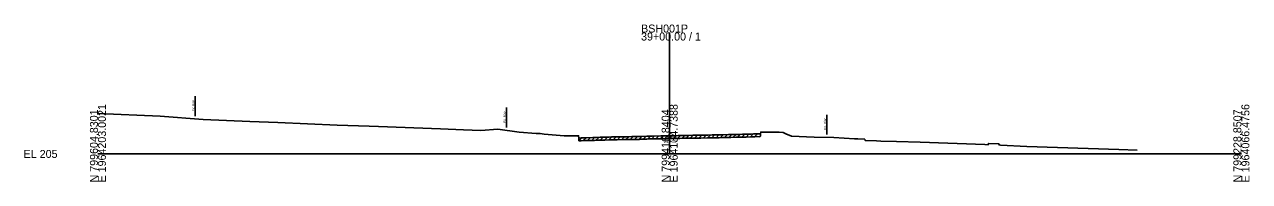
# Model space of a CAD drawing. Extents: x -26 to 1403, y -10 to 19587.
# Drawn here: x 974.3 to 1402.8, y 2990.3 to 3045.4 of the extents above; entities that cross this region are included whole.
import ezdxf

# ---------------------------------------------------------------- set-up
doc = ezdxf.new("R2010")
doc.units = 0
for name, color, linetype in [('Default', 7, 'Continuous'), ('RD_GPK_XS_Cell', 7, 'Continuous'), ('RD_XS_ExGround', 7, 'Continuous'), ('RD_XS_ExPaveRet', 7, 'Continuous'), ('RD_XS_ExRW', 7, 'Continuous'), ('RD_XS_TX_Elev_EX', 7, 'Continuous')]:
    doc.layers.add(name, color=color, linetype=linetype)

msp = doc.modelspace()

# ---------------------------------------------------------------- linework, layer by layer
at = {"layer": 'RD_GPK_XS_Cell'}
for p, q in [((1200, 3000), (1200, 3042.57)), ((1000, 3000), (1200, 3000)), ((1200, 3000), (1400, 3000))]:
    msp.add_line(p, q, dxfattribs=at)
at = {"layer": 'RD_XS_ExGround'}
msp.add_lwpolyline([(1000, 3014.19), (1021.82, 3013.19), (1036.85, 3012.04), (1053.19, 3011.37), (1062.94, 3010.97), (1083.68, 3010.09), (1094.83, 3009.69), (1098.19, 3009.56), (1119.78, 3008.79), (1127.84, 3008.44), (1133.92, 3008.16), (1139.86, 3008.66), (1147.36, 3007.64), (1153.27, 3007.2), (1154.72, 3007.11), (1156.1, 3006.98), (1163.13, 3006.38), (1165.49, 3006.35), (1168.12, 3006.37), (1168.19, 3005.55), (1169.06, 3005.64), (1170.25, 3005.67), (1170.89, 3005.68), (1173.15, 3005.74), (1173.74, 3005.76), (1174.27, 3005.77), (1175.71, 3005.82), (1176.22, 3005.84), (1177.3, 3005.87), (1178.87, 3005.93), (1179.6, 3005.95), (1181.59, 3005.99), (1184.16, 3006.02), (1185.43, 3006.04), (1186.82, 3006.06), (1188.89, 3006.1), (1189.47, 3006.11), (1189.91, 3006.12), (1192.03, 3006.19), (1192.86, 3006.24), (1193.89, 3006.27), (1196.95, 3006.35), (1197.67, 3006.34), (1198.82, 3006.35), (1200.14, 3006.35), (1202.35, 3006.4), (1202.99, 3006.41), (1203.55, 3006.43), (1204.97, 3006.48), (1205.47, 3006.49), (1206.15, 3006.5), (1206.75, 3006.51), (1208.13, 3006.54), (1210.9, 3006.57), (1213.43, 3006.61), (1214.88, 3006.64), (1216.09, 3006.66), (1217.36, 3006.69), (1218.62, 3006.72), (1220.54, 3006.78), (1221.38, 3006.8), (1223.19, 3006.84), (1224.05, 3006.86), (1225.53, 3006.9), (1226.39, 3006.92), (1226.71, 3006.93), (1228.35, 3006.98), (1229.36, 3007.01), (1229.83, 3007.03), (1230.72, 3007.06), (1231.52, 3007.05), (1231.78, 3007.2), (1231.88, 3007.65), (1235.01, 3007.68), (1236.92, 3007.67), (1238.32, 3007.59), (1239.75, 3007.48), (1240.69, 3007.09), (1242.66, 3006.17), (1250.54, 3005.87), (1257.41, 3005.71), (1264.7, 3005.33), (1265.88, 3005.3), (1268.27, 3005.17), (1268.37, 3004.72), (1272.32, 3004.55), (1273.88, 3004.47), (1279.38, 3004.35), (1287.62, 3004.07), (1310.23, 3003.25), (1311.43, 3003.21), (1311.53, 3003.66), (1315.15, 3003.59), (1315.25, 3003.14), (1315.77, 3003.11), (1324.96, 3002.57), (1357.12, 3001.58), (1363.52, 3001.36)], dxfattribs=at)
at = {"layer": 'RD_XS_ExPaveRet'}
for p, q in [((1168.22, 3004.55), (1169.31, 3005.64)), ((1168.22, 3004.55), (1168.22, 3005.55)), ((1168.22, 3004.55), (1169.06, 3004.64)), ((1169.06, 3004.64), (1170.25, 3004.67)), ((1169.72, 3004.65), (1170.74, 3005.67)), ((1170.25, 3004.67), (1170.89, 3004.68)), ((1170.89, 3004.68), (1173.15, 3004.74)), ((1171.22, 3004.69), (1172.25, 3005.71)), ((1172.72, 3004.73), (1173.75, 3005.76)), ((1173.15, 3004.74), (1173.74, 3004.76)), ((1173.74, 3004.76), (1174.27, 3004.77)), ((1174.22, 3004.77), (1175.26, 3005.81)), ((1174.27, 3004.77), (1175.71, 3004.82)), ((1175.71, 3004.82), (1176.22, 3004.84)), ((1175.72, 3004.82), (1176.76, 3005.86)), ((1176.22, 3004.84), (1177.3, 3004.87)), ((1177.22, 3004.87), (1178.26, 3005.91)), ((1177.3, 3004.87), (1178.87, 3004.93)), ((1178.72, 3004.92), (1179.75, 3005.95)), ((1178.87, 3004.93), (1179.6, 3004.95)), ((1179.6, 3004.95), (1181.59, 3004.99)), ((1180.22, 3004.96), (1181.24, 3005.99)), ((1181.59, 3004.99), (1184.16, 3005.02)), ((1181.72, 3004.99), (1182.73, 3006)), ((1183.22, 3005.01), (1184.23, 3006.02)), ((1184.16, 3005.02), (1185.43, 3005.04)), ((1184.72, 3005.02), (1185.74, 3006.04)), ((1185.43, 3005.04), (1186.82, 3005.06)), ((1186.22, 3005.05), (1187.24, 3006.07)), ((1186.82, 3005.06), (1188.89, 3005.1)), ((1187.72, 3005.08), (1188.74, 3006.1)), ((1188.89, 3005.1), (1189.47, 3005.11)), ((1189.22, 3005.1), (1190.25, 3006.13)), ((1189.47, 3005.11), (1189.91, 3005.12)), ((1189.91, 3005.12), (1192.03, 3005.19)), ((1190.72, 3005.15), (1191.75, 3006.18)), ((1192.03, 3005.19), (1192.86, 3005.24)), ((1192.22, 3005.2), (1193.27, 3006.25)), ((1192.86, 3005.24), (1193.89, 3005.27)), ((1193.72, 3005.26), (1194.75, 3006.29)), ((1193.89, 3005.27), (1196.95, 3005.35)), ((1195.22, 3005.3), (1196.25, 3006.33)), ((1196.72, 3005.34), (1197.71, 3006.34)), ((1196.95, 3005.35), (1197.67, 3005.34)), ((1197.67, 3005.34), (1198.82, 3005.35)), ((1198.22, 3005.34), (1199.23, 3006.35)), ((1198.82, 3005.35), (1200.14, 3005.35)), ((1199.72, 3005.35), (1200.74, 3006.37)), ((1200.14, 3005.35), (1202.35, 3005.4)), ((1201.22, 3005.38), (1202.24, 3006.4)), ((1202.35, 3005.4), (1202.99, 3005.41)), ((1202.72, 3005.41), (1203.75, 3006.44)), ((1202.99, 3005.41), (1203.55, 3005.43)), ((1203.55, 3005.43), (1204.97, 3005.48)), ((1204.22, 3005.45), (1205.25, 3006.48)), ((1204.97, 3005.48), (1205.47, 3005.49)), ((1205.47, 3005.49), (1206.15, 3005.5)), ((1205.72, 3005.49), (1206.74, 3006.51)), ((1206.15, 3005.5), (1206.75, 3005.51)), ((1206.75, 3005.51), (1208.13, 3005.54)), ((1207.22, 3005.52), (1208.24, 3006.54)), ((1208.13, 3005.54), (1210.9, 3005.57)), ((1208.72, 3005.54), (1209.73, 3006.55)), ((1210.22, 3005.56), (1211.24, 3006.57)), ((1210.9, 3005.57), (1213.43, 3005.61)), ((1211.72, 3005.58), (1212.74, 3006.6)), ((1213.22, 3005.61), (1214.24, 3006.63)), ((1213.43, 3005.61), (1214.88, 3005.64)), ((1214.72, 3005.64), (1215.74, 3006.66)), ((1214.88, 3005.64), (1216.09, 3005.66)), ((1216.09, 3005.66), (1217.36, 3005.69)), ((1216.22, 3005.67), (1217.25, 3006.69)), ((1217.36, 3005.69), (1218.62, 3005.72)), ((1217.72, 3005.7), (1218.75, 3006.73)), ((1218.62, 3005.72), (1220.54, 3005.78)), ((1219.22, 3005.74), (1220.25, 3006.77)), ((1220.54, 3005.78), (1221.38, 3005.8)), ((1220.72, 3005.78), (1221.74, 3006.81)), ((1221.38, 3005.8), (1223.19, 3005.84)), ((1222.22, 3005.82), (1223.25, 3006.84)), ((1223.19, 3005.84), (1224.05, 3005.86)), ((1223.72, 3005.85), (1224.75, 3006.88)), ((1224.05, 3005.86), (1225.53, 3005.9)), ((1225.22, 3005.89), (1226.25, 3006.91)), ((1225.53, 3005.9), (1226.39, 3005.92)), ((1226.39, 3005.92), (1226.71, 3005.93)), ((1226.71, 3005.93), (1228.35, 3005.98)), ((1226.72, 3005.93), (1227.75, 3006.96)), ((1228.22, 3005.97), (1229.25, 3007.01)), ((1228.35, 3005.98), (1229.36, 3006.01)), ((1229.36, 3006.01), (1229.83, 3006.03)), ((1229.72, 3006.02), (1230.76, 3007.06)), ((1229.83, 3006.03), (1230.72, 3006.06)), ((1230.72, 3006.06), (1231.52, 3006.05)), ((1231.52, 3006.05), (1231.78, 3006.2)), ((1231.78, 3007.2), (1231.78, 3006.2))]:
    msp.add_line(p, q, dxfattribs=at)
at = {"layer": 'RD_XS_ExRW'}
for p, q in [((1034.05, 3013.25), (1034.05, 3020.25)), ((1142.96, 3009.24), (1142.96, 3016.24)), ((1254.95, 3006.76), (1254.95, 3013.76))]:
    msp.add_line(p, q, dxfattribs=at)

# ---------------------------------------------------------------- texts
at = {"layer": 'Default'}
msp.add_text('-', height=0.0001, dxfattribs=at).set_placement((1000, 3000))
at = {"layer": 'RD_GPK_XS_Cell'}
for s, p in [('39+00.00 / 1', (1190, 3039.77)), ('BSH001P', (1190, 3042.57)), ('EL 205', (974, 2998.6))]:
    msp.add_text(s, height=2.8, dxfattribs=at).set_placement(p)
for s, p in [('E 1964203.0021', (1002.8, 2990)), ('E 1964134.7388', (1202.8, 2990)), ('E 1964066.4756', (1402.8, 2990)), ('N 799604.8301', (1000, 2990)), ('N 799416.8404', (1200, 2990)), ('N 799228.8507', (1400, 2990))]:
    msp.add_text(s, height=2.8, rotation=90, dxfattribs=at).set_placement(p)
at = {"layer": 'RD_XS_ExRW'}
for p in [(1033.8, 3014.93), (1142.71, 3010.91), (1254.7, 3008.44)]:
    msp.add_text('EX. R/W ', height=0.75, rotation=90, dxfattribs=at).set_placement(p)
at = {"layer": 'RD_XS_TX_Elev_EX'}
msp.add_text('211.35', height=1, dxfattribs=at).set_placement((1197.95, 3003.85))

doc.saveas('drawing.dxf')
